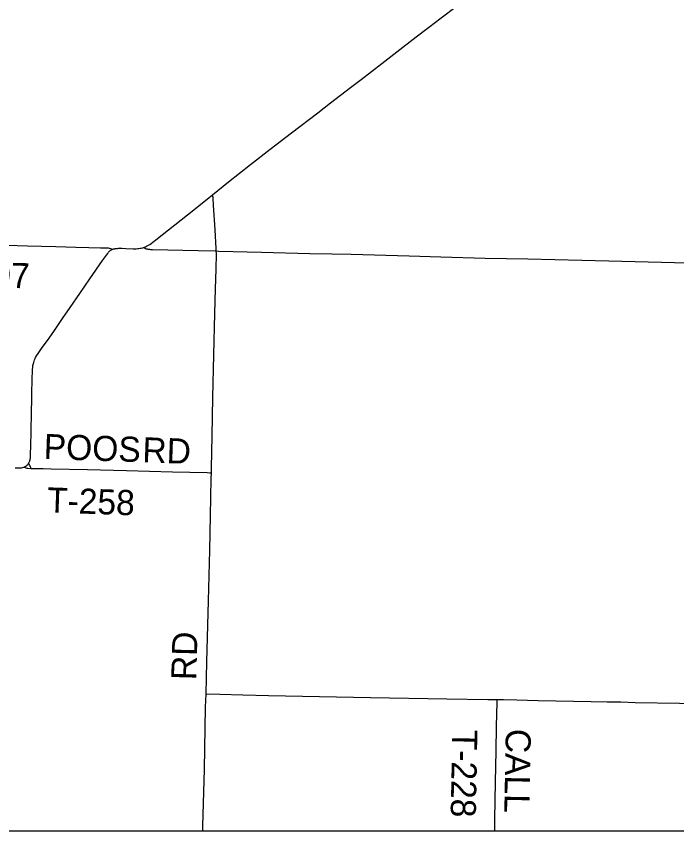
# Model space of a CAD drawing. Extents: x 1341221 to 1914484, y 79347 to 658398.
# Drawn here: x 1359400 to 1374791, y 580425 to 599399 of the extents above; entities that cross this region are included whole.
import ezdxf

# ---------------------------------------------------------------- set-up
doc = ezdxf.new("R2010")
doc.units = 0
for name, color, linetype in [('GM_X_Major_Lake_Text', 7, 'Continuous'), ('GM_X_Major_River_Text', 7, 'Continuous'), ('GM_X_Minor_Lake_Text', 7, 'Continuous'), ('GM_X_State_Location', 7, 'Continuous'), ('GM_X_Township_Text', 7, 'Continuous'), ('GM_X_US_Shield', 7, 'Continuous')]:
    doc.layers.add(name, color=color, linetype=linetype)

msp = doc.modelspace()

# ---------------------------------------------------------------- linework, layer by layer
at = {"layer": 'GM_X_Minor_Lake_Text'}
msp.add_lwpolyline([(1435650, 641695), (1348099, 641695), (1348099, 580425), (1435650, 580425)], close=True, dxfattribs=at)
at = {"layer": 'GM_X_State_Location'}
for points in [[(1369197, 599284), (1369239, 599316), (1369336, 599389), (1369617, 599601), (1369739, 599687), (1369792, 599722), (1369899, 599790), (1370152, 599941), (1371027, 600446), (1371722, 600842), (1372205, 601120), (1372852, 601483), (1373372, 601772), (1375078, 602744), (1375736, 603114), (1375804, 603153), (1376176, 603363), (1376498, 603548), (1376965, 603813), (1377238, 603969), (1378266, 604560), (1378605, 604754)], [(1362365, 594012), (1362414, 594031), (1362435, 594041), (1362465, 594058), (1362508, 594085), (1362609, 594159), (1362649, 594189), (1363539, 594890), (1363898, 595179), (1363969, 595237), (1364343, 595545), (1364856, 595948), (1365317, 596303), (1365815, 596684), (1366426, 597149), (1366726, 597379), (1367192, 597738), (1367434, 597926), (1367915, 598299), (1368269, 598572), (1368719, 598921), (1368973, 599116), (1369197, 599284)], [(1359374, 588877), (1359468, 588880), (1359519, 588882), (1359545, 588886), (1359579, 588897), (1359608, 588911), (1359632, 588926), (1359651, 588942), (1359663, 588955), (1359677, 588971), (1359685, 588984), (1359700, 589008), (1359709, 589027), (1359714, 589041), (1359720, 589065), (1359725, 589089), (1359728, 589111), (1359734, 589182), (1359739, 589406), (1359746, 589700), (1359749, 589821), (1359753, 590083), (1359764, 590570), (1359770, 590979), (1359775, 591114), (1359778, 591171), (1359783, 591222), (1359789, 591266), (1359798, 591306), (1359805, 591335), (1359814, 591367), (1359825, 591396), (1359838, 591425), (1359849, 591447), (1359872, 591489), (1359907, 591546), (1359988, 591662), (1360162, 591899), (1360287, 592077), (1360478, 592357), (1360655, 592616), (1360881, 592942), (1361115, 593285), (1361409, 593710), (1361500, 593836), (1361530, 593876), (1361551, 593901), (1361566, 593917), (1361573, 593924), (1361582, 593932), (1361590, 593939), (1361601, 593947), (1361616, 593956), (1361635, 593966), (1361646, 593971)], [(1361646, 593971), (1361666, 593978), (1361680, 593982), (1361695, 593985), (1361705, 593987), (1361722, 593990), (1361736, 593991), (1361757, 593992), (1361779, 593994), (1361822, 593995), (1361856, 593994), (1361952, 593990), (1362124, 593985), (1362195, 593985), (1362236, 593987), (1362258, 593989), (1362288, 593993), (1362311, 593997), (1362352, 594007), (1362365, 594012)]]:
    msp.add_lwpolyline(points, dxfattribs=at)
at = {"layer": 'GM_X_Township_Text'}
for points in [[(1364061, 593931), (1364060, 593991), (1364036, 594421), (1363998, 594995), (1363989, 595152), (1363988, 595168), (1363986, 595181), (1363983, 595196), (1363979, 595210), (1363975, 595222), (1363969, 595237)], [(1363747, 580425), (1363749, 580537), (1363785, 581848), (1363813, 583306), (1363822, 583611), (1363843, 584362), (1363878, 585781), (1363908, 586958), (1363926, 587764), (1363945, 588634), (1363950, 588765), (1363952, 588871), (1363967, 589625), (1363983, 590514), (1364005, 591513), (1364028, 592472), (1364040, 593047), (1364054, 593508), (1364062, 593861), (1364061, 593931)], [(1359741, 588867), (1359735, 588888), (1359728, 588904), (1359723, 588919), (1359711, 588944), (1359699, 588962), (1359685, 588984)], [(1359579, 588897), (1359606, 588885), (1359624, 588877), (1359644, 588871), (1359671, 588868), (1359741, 588867), (1360023, 588863), (1360215, 588859), (1361058, 588838), (1361971, 588815), (1363039, 588787), (1363846, 588769), (1363913, 588766), (1363950, 588765)], [(1363822, 583611), (1364146, 583603), (1364677, 583592), (1365278, 583578), (1367657, 583528), (1369436, 583495), (1370389, 583483), (1370607, 583479), (1370751, 583483), (1371065, 583471), (1371565, 583460), (1372800, 583432), (1373171, 583426), (1373489, 583424), (1373823, 583414), (1374859, 583395), (1375709, 583387), (1376380, 583371), (1376765, 583357), (1377206, 583347), (1378378, 583333), (1378434, 583333)], [(1370549, 580425), (1370553, 580695), (1370571, 581558), (1370583, 582287), (1370594, 582850), (1370604, 583418), (1370607, 583479)]]:
    msp.add_lwpolyline(points, dxfattribs=at)
at = {"layer": 'GM_X_US_Shield'}
for points in [[(1359182, 594064), (1359663, 594052), (1359991, 594043), (1360320, 594034), (1360787, 594022), (1361087, 594014), (1361362, 594007), (1361400, 594006), (1361499, 594004), (1361538, 594001), (1361566, 593997), (1361596, 593990), (1361622, 593980), (1361646, 593971)], [(1361646, 593971), (1361666, 593978), (1361680, 593982), (1361695, 593985), (1361705, 593987), (1361722, 593990), (1361736, 593991), (1361757, 593992), (1361779, 593994), (1361822, 593995), (1361856, 593994), (1361952, 593990), (1362124, 593985), (1362195, 593985), (1362236, 593987), (1362258, 593989), (1362288, 593993), (1362311, 593997), (1362352, 594007), (1362365, 594012)], [(1362365, 594012), (1362399, 593993), (1362412, 593987), (1362422, 593984), (1362436, 593980), (1362451, 593978), (1362467, 593975), (1362501, 593972), (1362531, 593969), (1362572, 593967), (1363641, 593941), (1364061, 593931), (1364120, 593930), (1365111, 593903), (1366237, 593874), (1366755, 593861), (1367203, 593854), (1368553, 593817), (1369294, 593797), (1370324, 593766), (1371321, 593746), (1373211, 593703), (1374742, 593659), (1376124, 593625)]]:
    msp.add_lwpolyline(points, dxfattribs=at)

# ---------------------------------------------------------------- texts
at = {"layer": 'GM_X_Major_Lake_Text'}
msp.add_text('C-97', height=585, rotation=358.9714, dxfattribs=at).set_placement((1358015, 593091))
at = {"layer": 'GM_X_Major_River_Text'}
for s, rotation, p in [('POOS', 358.1177, (1360032, 589086)), ('RD', 358.0243, (1362331, 589009)), ('T-258', 358.0348, (1360109, 587841)), ('RD', 88.5184, (1363595, 583928)), ('T-228', 268.8765, (1369562, 582784)), ('CALL', 268.9486, (1370808, 582803))]:
    msp.add_text(s, height=585, rotation=rotation, dxfattribs=at).set_placement(p)

doc.saveas('drawing.dxf')
